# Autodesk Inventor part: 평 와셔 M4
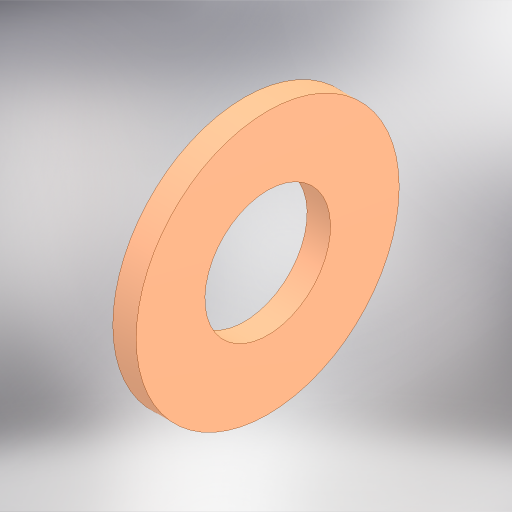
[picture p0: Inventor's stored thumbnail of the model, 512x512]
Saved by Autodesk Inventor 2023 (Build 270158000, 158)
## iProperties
Created: 2026-07
Part Number: 평 와셔 M4
Material: 강철, 연강
Description: 평면 와셔
Document SubType Name: Modeling
Designer: home
Density: 7.85 g/cm^3
Appearance: 기본값
Author: jhkim
Sending System: Autodesk Inventor 2027
Preprocessor: ST-DEVELOPER v20.1
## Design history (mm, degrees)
feature "Solid1"
node "솔리드1"
